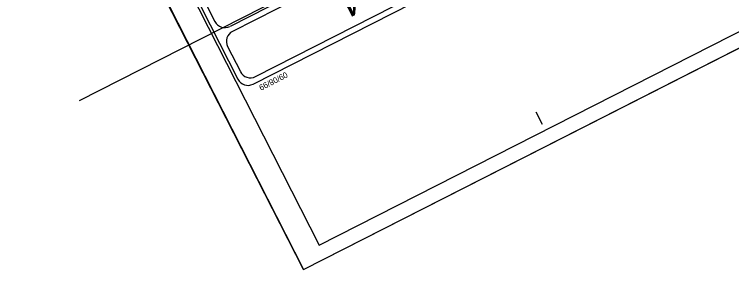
# Model space of a CAD drawing. Extents: x 558484 to 564063, y 513718 to 518374.
# Drawn here: x 559154 to 559790, y 514425 to 514651 of the extents above; entities that cross this region are included whole.
import ezdxf

# ---------------------------------------------------------------- set-up
doc = ezdxf.new("R2010")
doc.units = 0
for name, color, linetype in [('Scratch_Level_3', 7, 'Continuous'), ('Sheet Cutting Line CELL', 7, 'Continuous'), ('Sheet Plot Border Inside CELL', 7, 'Continuous'), ('Sheet Plot Border Outside CELL', 7, 'Continuous'), ('Sheet Title CELL', 7, 'Continuous')]:
    doc.layers.add(name, color=color, linetype=linetype)

msp = doc.modelspace()

# ---------------------------------------------------------------- linework, layer by layer
at = {"layer": 'Scratch_Level_3'}
msp.add_line((559481.39, 514712.08), (559211.34, 514574.59), dxfattribs=at)
at = {"layer": 'Sheet Cutting Line CELL'}
for q in [(558646.11, 515925.37), (560390.41, 514923.75)]:
    msp.add_line((559410.15, 514424.68), q, dxfattribs=at)
at = {"layer": 'Sheet Plot Border Inside CELL'}
msp.add_lwpolyline([(560364.51, 514925.16), (559608.41, 516410.26), (558668.16, 515931.55), (559424.26, 514446.45)], close=True, dxfattribs=at)
at = {"layer": 'Sheet Plot Border Outside CELL'}
msp.add_lwpolyline([(558646.11, 515925.37), (559410.15, 514424.68), (560390.41, 514923.75), (559626.36, 516424.45)], close=True, dxfattribs=at)
at = {"layer": 'Sheet Title CELL'}
for p, q in [((560256.31, 515098.98), (559347.33, 514636.2)), ((560089.18, 515019.5), (559345.07, 514640.66)), ((559622.32, 514553.46), (559616.65, 514564.6)), ((559622.32, 514553.46), (559616.65, 514564.6))]:
    msp.add_line(p, q, dxfattribs=at)
for points in [[(558680.63, 515912.67), (559352.12, 514593.74)], [(558687.36, 515910.47), (559331.62, 514645.05)], [(559365.56, 514589.37), (560283.45, 515056.69)], [(559365.56, 514589.37), (560283.45, 515056.69)], [(559367.75, 514596.11), (560276.72, 515058.88)], [(559342.97, 514622.76), (559354.3, 514600.47)]]:
    msp.add_lwpolyline(points, dxfattribs=at)
for centre, start, end in [((559340.49, 514649.55), 206.98193, 296.98193), ((559351.83, 514627.27), 116.98193, 206.98193), ((559363.17, 514604.99), 206.98193, 296.98193), ((559360.98, 514598.27), 206.98193, 296.98193)]:
    msp.add_arc(centre, 10, start, end, dxfattribs=at)

# ---------------------------------------------------------------- texts
for s, height, p in [('B-4734  ', 25, (559534.25, 514718.59)), ('09/08/99', 5.25, (559394.55, 514600.49))]:
    msp.add_text(s, height=height, rotation=206.98193, dxfattribs=at).set_placement(p)

doc.saveas('drawing.dxf')
